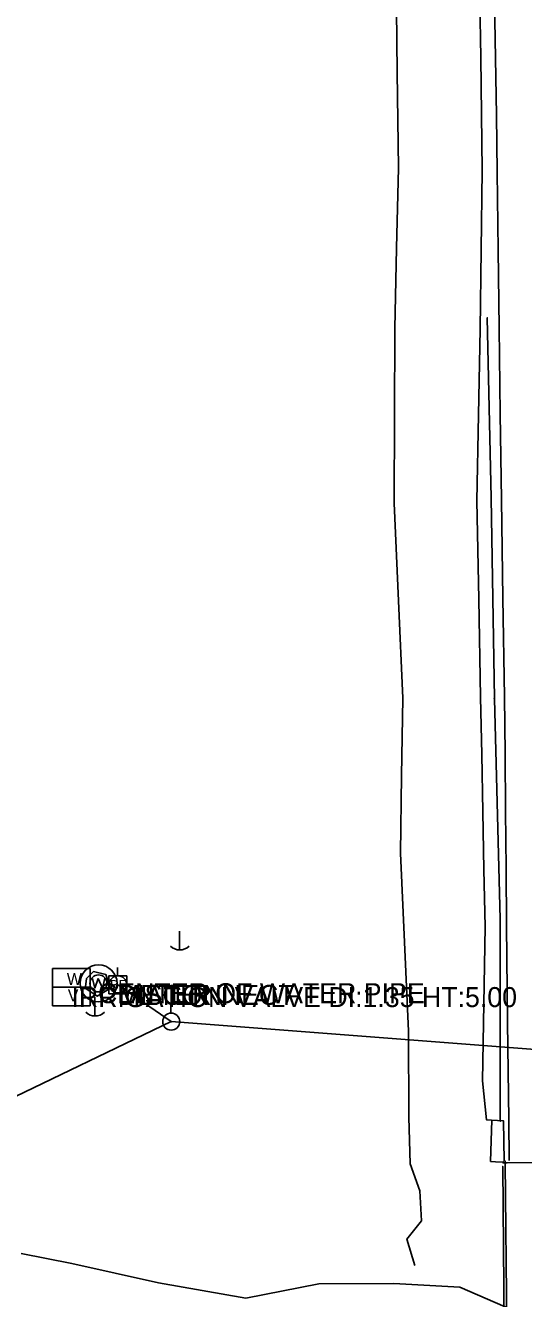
# Model space of a CAD drawing. Extents: x 1676038 to 1677961, y 226475 to 233854.
# Drawn here: x 1677241.7 to 1677366.3, y 229139.3 to 229457.9 of the extents above; entities that cross this region are included whole.
import ezdxf

# ---------------------------------------------------------------- set-up
doc = ezdxf.new("R2010")
doc.units = 0
for name, color, linetype in [('S_BRIDGE', 7, 'Continuous'), ('S_DITCHLINE', 7, 'Continuous'), ('S_EDGE_CONCRETE', 7, 'Continuous'), ('S_EDGE_PAVEMENT', 7, 'Continuous'), ('S_ELECTRIC_UTILITIES', 7, 'Continuous'), ('S_ELECTRIC_UTILITIES_ANNOT', 7, 'Continuous'), ('S_GUARDRAIL', 7, 'Continuous'), ('S_RDW_PT_SYM', 7, 'Continuous'), ('S_SHOULDER', 7, 'Continuous'), ('S_STR_PT_SYM', 7, 'Continuous'), ('S_STREAM', 7, 'Continuous'), ('S_UTILITY_POLE', 7, 'Continuous'), ('S_UTL_PT_SYM', 7, 'Continuous'), ('S_WATER_UTILITIES', 7, 'Continuous'), ('S_WATER_UTILITIES_ANNOT', 7, 'Continuous'), ('S_WATER_WELL_ANNOT', 7, 'Continuous')]:
    doc.layers.add(name, color=color, linetype=linetype)

msp = doc.modelspace()

# ---------------------------------------------------------------- linework, layer by layer
at = {"layer": 'S_BRIDGE'}
for p, q in [((1677387.46, 229173.43), (1677361.66, 229173.27)), ((1677361.66, 229173.27), (1677362.11, 229129.12))]:
    msp.add_line(p, q, dxfattribs=at)
at = {"layer": 'S_DITCHLINE'}
msp.add_lwpolyline([(1677339.09, 229147.6), (1677337.05, 229154.23), (1677340.76, 229158.8), (1677340.29, 229166.32), (1677337.9, 229173.01), (1677337.54, 229184.7), (1677337.47, 229206.29), (1677336.46, 229228.55), (1677335.46, 229250.81), (1677335.75, 229270.19), (1677336.05, 229289.58), (1677334.99, 229313.98), (1677333.93, 229338.37), (1677333.99, 229360.23), (1677334.04, 229382.08), (1677334.5, 229402.19), (1677334.96, 229422.29), (1677334.69, 229446.15), (1677334.41, 229470.02), (1677334.41, 229473.73)], dxfattribs=at)
at = {"layer": 'S_EDGE_CONCRETE'}
msp.add_lwpolyline([(1677256.8, 229216.96), (1677259.63, 229214.99), (1677262.93, 229217), (1677261.81, 229220.41), (1677258.73, 229221.18), (1677256.93, 229219.41), (1677256.67, 229217.35)], close=True, dxfattribs=at)
msp.add_lwpolyline([(1677361.33, 229173.44), (1677359.28, 229173.57), (1677358.03, 229173.64), (1677358.3, 229183.99)], dxfattribs=at)
at = {"layer": 'S_EDGE_PAVEMENT'}
msp.add_lwpolyline([(1677362.64, 229173.87), (1677362.58, 229184.14), (1677362.3, 229208.4), (1677362.03, 229232.67), (1677361.91, 229246.99), (1677361.78, 229261.3), (1677361.66, 229275.62), (1677361.54, 229289.94), (1677361.13, 229314.58), (1677360.72, 229339.22), (1677360.46, 229360.76), (1677360.2, 229382.3), (1677359.96, 229401.74), (1677359.71, 229421.19), (1677359.47, 229435.45), (1677359.23, 229449.72), (1677359, 229463.99)], dxfattribs=at)
at = {"layer": 'S_ELECTRIC_UTILITIES'}
for p, q in [((1677278.13, 229208.63), (1677264.79, 229217.83)), ((1677278.13, 229208.63), (1677031.23, 229090)), ((1677541.68, 229188.35), (1677278.13, 229208.63))]:
    msp.add_line(p, q, dxfattribs=at)
for points in [[(1677262.52, 229215.58), (1677262.52, 229220.08), (1677267.02, 229220.08), (1677267.02, 229215.58)], [(1677262.53, 229215.58), (1677262.53, 229220.08), (1677267.03, 229220.08), (1677267.03, 229215.58)]]:
    msp.add_lwpolyline(points, close=True, dxfattribs=at)
at = {"layer": 'S_GUARDRAIL'}
for p, q in [((1677358.16, 229339.7), (1677357.21, 229384.75)), ((1677358.97, 229289.43), (1677358.16, 229339.7)), ((1677360.43, 229234.31), (1677358.97, 229289.43)), ((1677360.45, 229183.75), (1677360.43, 229234.31)), ((1677361.48, 229129.27), (1677361.06, 229172.37))]:
    msp.add_line(p, q, dxfattribs=at)
at = {"layer": 'S_RDW_PT_SYM'}
for points in [[(1677357.21, 229384.75), (1677357.21, 229384.8), (1677357.21, 229384.75), (1677357.16, 229384.75), (1677357.21, 229384.75), (1677357.21, 229384.7), (1677357.21, 229384.75), (1677357.26, 229384.75)], [(1677358.16, 229339.7), (1677358.16, 229339.75), (1677358.16, 229339.7), (1677358.11, 229339.7), (1677358.16, 229339.7), (1677358.16, 229339.65), (1677358.16, 229339.7), (1677358.21, 229339.7)], [(1677358.97, 229289.43), (1677358.97, 229289.48), (1677358.97, 229289.43), (1677358.92, 229289.43), (1677358.97, 229289.43), (1677358.97, 229289.38), (1677358.97, 229289.43), (1677359.02, 229289.43)], [(1677360.43, 229234.31), (1677360.43, 229234.36), (1677360.43, 229234.31), (1677360.38, 229234.31), (1677360.43, 229234.31), (1677360.43, 229234.26), (1677360.43, 229234.31), (1677360.48, 229234.31)], [(1677360.45, 229183.75), (1677360.45, 229183.8), (1677360.45, 229183.75), (1677360.4, 229183.75), (1677360.45, 229183.75), (1677360.45, 229183.7), (1677360.45, 229183.75), (1677360.5, 229183.75)], [(1677361.06, 229172.37), (1677361.06, 229172.42), (1677361.06, 229172.37), (1677361.01, 229172.37), (1677361.06, 229172.37), (1677361.06, 229172.32), (1677361.06, 229172.37), (1677361.11, 229172.37)]]:
    msp.add_lwpolyline(points, dxfattribs=at)
at = {"layer": 'S_SHOULDER'}
msp.add_lwpolyline([(1677361.46, 229173.68), (1677361.22, 229183.83), (1677358.23, 229184.01), (1677356.99, 229184.09), (1677356.02, 229193.79), (1677356.33, 229213.09), (1677356.64, 229232.38), (1677356.36, 229246.75), (1677356.09, 229261.12), (1677355.81, 229275.49), (1677355.54, 229289.86), (1677355.06, 229314.39), (1677354.58, 229338.93), (1677355.01, 229360.45), (1677355.43, 229381.96), (1677355.69, 229401.78), (1677355.95, 229421.6), (1677355.75, 229435.77), (1677355.56, 229449.95), (1677355.36, 229464.12)], dxfattribs=at)
at = {"layer": 'S_STR_PT_SYM'}
msp.add_lwpolyline([(1677361.66, 229173.27), (1677361.66, 229173.77), (1677361.66, 229173.27), (1677361.16, 229173.27), (1677361.66, 229173.27), (1677361.66, 229172.77), (1677361.66, 229173.27), (1677362.16, 229173.27)], dxfattribs=at)
at = {"layer": 'S_STREAM'}
msp.add_lwpolyline([(1677363.56, 229136.47), (1677350.31, 229142.22), (1677333.85, 229143.1), (1677315.1, 229143.02), (1677296.79, 229139.47), (1677274.96, 229143.23), (1677253.24, 229148.13), (1677240.58, 229150.59)], dxfattribs=at)
at = {"layer": 'S_UTILITY_POLE'}
for p, q in [((1677280.21, 229231.29), (1677280.21, 229226.56)), ((1677264.7, 229220.1), (1677264.7, 229222.21)), ((1677259.03, 229214.76), (1677259.03, 229210.03)), ((1677278.01, 229210.77), (1677278.01, 229212.88))]:
    msp.add_line(p, q, dxfattribs=at)
for centre in [(1677264.82, 229217.96), (1677278.13, 229208.63)]:
    msp.add_circle(centre, 2.13, dxfattribs=at)
for centre in [(1677280.27, 229229.99), (1677259.09, 229213.46)]:
    msp.add_arc(centre, 3.41, 226.3972, 313.6028, dxfattribs=at)
at = {"layer": 'S_UTL_PT_SYM'}
for points in [[(1677264.79, 229217.83), (1677264.79, 229217.88), (1677264.79, 229217.83), (1677264.74, 229217.83), (1677264.79, 229217.83), (1677264.79, 229217.78), (1677264.79, 229217.83), (1677264.84, 229217.83)], [(1677278.13, 229208.63), (1677278.13, 229208.68), (1677278.13, 229208.63), (1677278.08, 229208.63), (1677278.13, 229208.63), (1677278.13, 229208.58), (1677278.13, 229208.63), (1677278.18, 229208.63)], [(1677278.13, 229208.63), (1677278.13, 229208.68), (1677278.13, 229208.63), (1677278.08, 229208.63), (1677278.13, 229208.63), (1677278.13, 229208.58), (1677278.13, 229208.63), (1677278.18, 229208.63)]]:
    msp.add_lwpolyline(points, dxfattribs=at)
at = {"layer": 'S_WATER_UTILITIES'}
for p, q in [((1677248.46, 229221.97), (1677257.88, 229221.97)), ((1677248.46, 229212.56), (1677248.46, 229221.97)), ((1677257.88, 229221.97), (1677257.88, 229212.56)), ((1677258.4, 229219.47), (1677259.06, 229216.99)), ((1677259.06, 229216.99), (1677259.87, 229219.47)), ((1677259.87, 229219.47), (1677260.92, 229216.99)), ((1677260.92, 229216.99), (1677261.5, 229219.51)), ((1677248.46, 229217.28), (1677257.88, 229217.28)), ((1677257.88, 229212.56), (1677248.46, 229212.56))]:
    msp.add_line(p, q, dxfattribs=at)
for centre, radius in [((1677259.96, 229218.21), 4.63), ((1677259.93, 229218.21), 2.13)]:
    msp.add_circle(centre, radius, dxfattribs=at)

# ---------------------------------------------------------------- texts
at = {"layer": 'S_ELECTRIC_UTILITIES'}
for p in [(1677262.84, 229216.63), (1677262.85, 229216.63)]:
    msp.add_text('BE', height=2.4, rotation=360, dxfattribs=at).set_placement(p)
at = {"layer": 'S_ELECTRIC_UTILITIES_ANNOT'}
for s, p in [('DISCONNECT', (1677264.79, 229212.83)), ('METER', (1677264.8, 229212.83))]:
    msp.add_text(s, height=5, dxfattribs=at).set_placement(p)
at = {"layer": 'S_WATER_UTILITIES'}
for s, p in [('W', (1677252.01, 229217.81)), ('V', (1677252.25, 229213.75))]:
    msp.add_text(s, height=3, rotation=360, dxfattribs=at).set_placement(p)
at = {"layer": 'S_WATER_UTILITIES_ANNOT'}
msp.add_text('IRRIGATION VALVE DI:1.35 HT:5.00', height=5, dxfattribs=at).set_placement((1677253.17, 229212.28))
at = {"layer": 'S_WATER_WELL_ANNOT'}
msp.add_text('CENTER OF WATER PIPE', height=5, dxfattribs=at).set_placement((1677259.81, 229213.25))

doc.saveas('drawing.dxf')
